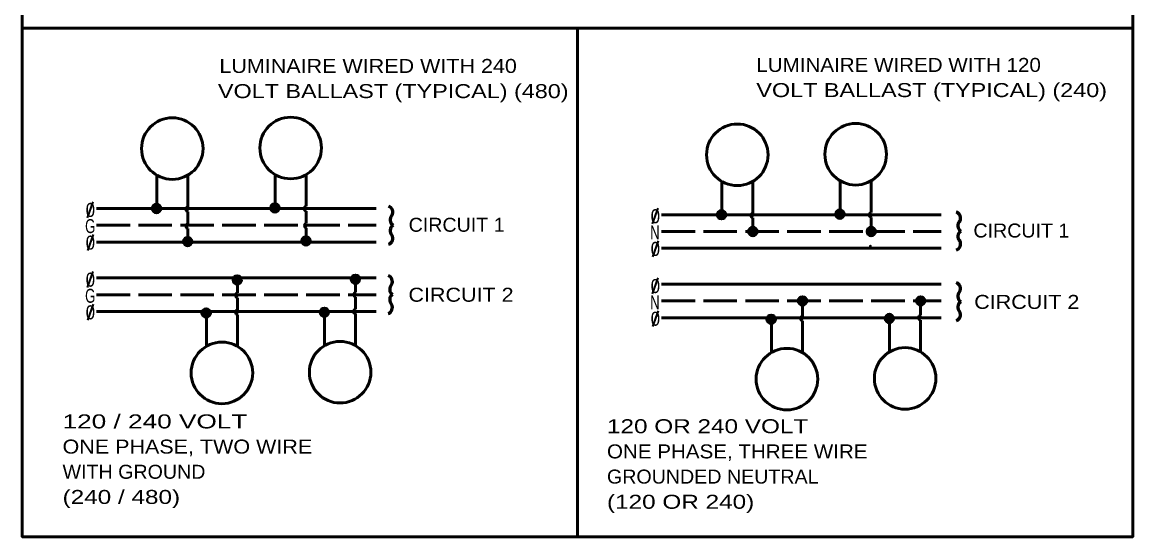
# Model space of a CAD drawing. Extents: x -217 to 639, y -295 to 249.
# Drawn here: x 241.3 to 479.6, y 13.4 to 123.7 of the extents above; entities that cross this region are included whole.
import ezdxf

# ---------------------------------------------------------------- set-up
doc = ezdxf.new("R2010")
doc.units = 0
doc.header["$LTSCALE"] = 1.2
doc.linetypes.add('LONG_DASHED', pattern=[7.5, 6, -1.5])
doc.layers.add('1', color=7, linetype='Continuous', lineweight=53)

msp = doc.modelspace()

# ---------------------------------------------------------------- hatches: boundary and pattern name
at = {"layer": '1'}
for points in [[(398.99, 78.859, 1), (397.19, 78.859, 1)], [(424.394, 78.859, 1), (422.594, 78.859, 1)], [(409.643, 63.979, 1), (407.843, 63.979, 1)], [(435.002, 63.979, 1), (433.202, 63.979, 1)]]:
    msp.add_hatch(color=256, dxfattribs=at).paths.add_polyline_path(points)

# ---------------------------------------------------------------- linework, layer by layer
for p, q in [((241.305, 122.435), (479.623, 122.435)), ((360.464, 122.435), (360.464, 13.402)), ((270.168, 83.678), (270.168, 90.949)), ((270.168, 83.678), (270.168, 90.949)), ((276.846, 84.158), (276.846, 90.948)), ((295.572, 83.805), (295.572, 91.076)), ((295.572, 83.805), (295.572, 91.076)), ((302.25, 84.285), (302.25, 91.076)), ((391.412, 82.341), (391.412, 89.612)), ((391.412, 82.341), (391.412, 89.612)), ((398.09, 82.821), (398.09, 89.612)), ((416.816, 82.469), (416.816, 89.739)), ((416.816, 82.469), (416.816, 89.739)), ((423.494, 82.948), (423.494, 89.739)), ((257.238, 83.796), (317.238, 83.796)), ((257.238, 83.796), (317.238, 83.796)), ((276.846, 80.535), (276.846, 83.107)), ((302.25, 80.663), (302.25, 83.235)), ((378.482, 82.459), (438.482, 82.459)), ((378.482, 82.459), (438.482, 82.459)), ((398.09, 78.859), (398.09, 81.77)), ((423.494, 78.859), (423.494, 81.898)), ((276.846, 76.625), (276.846, 79.479)), ((276.846, 76.625), (276.846, 79.479)), ((302.25, 76.753), (302.25, 79.606)), ((302.25, 76.753), (302.25, 79.606)), ((257.238, 76.596), (317.238, 76.596)), ((257.238, 76.596), (317.238, 76.596)), ((378.482, 75.259), (438.482, 75.259)), ((378.482, 75.259), (438.482, 75.259)), ((257.238, 68.916), (317.238, 68.916)), ((257.238, 68.916), (317.238, 68.916)), ((287.5, 68.559), (287.5, 65.705)), ((287.5, 68.559), (287.5, 65.705)), ((312.858, 68.706), (312.858, 65.852)), ((312.858, 68.706), (312.858, 65.852)), ((378.482, 67.579), (438.482, 67.579)), ((378.482, 67.579), (438.482, 67.579)), ((287.5, 64.649), (287.5, 62.076)), ((312.858, 64.796), (312.858, 62.224)), ((408.743, 63.979), (408.743, 60.739)), ((434.102, 63.979), (434.102, 60.887)), ((257.238, 61.716), (317.238, 61.716)), ((257.238, 61.716), (317.238, 61.716)), ((280.822, 61.506), (280.822, 54.235)), ((280.822, 61.506), (280.822, 54.235)), ((287.5, 61.026), (287.5, 54.235)), ((306.18, 61.653), (306.18, 54.383)), ((312.858, 61.174), (312.858, 54.383)), ((378.482, 60.379), (438.482, 60.379)), ((378.482, 60.379), (438.482, 60.379)), ((402.065, 60.169), (402.065, 52.898)), ((402.065, 60.169), (402.065, 52.898)), ((408.743, 59.689), (408.743, 52.898)), ((427.424, 60.317), (427.424, 53.046)), ((434.102, 59.837), (434.102, 53.046))]:
    msp.add_line(p, q, dxfattribs=at)
at = {"layer": '1', "lineweight": 35}
for p, q in [((256.478, 85.226), (255.241, 81.826)), ((377.722, 83.889), (376.484, 80.489)), ((256.538, 78.196), (255.3, 74.797)), ((377.781, 76.859), (376.544, 73.46)), ((256.478, 70.282), (255.241, 66.883)), ((377.722, 68.913), (376.484, 65.514)), ((256.538, 63.252), (255.3, 59.853)), ((377.781, 61.883), (376.544, 58.484))]:
    msp.add_line(p, q, dxfattribs=at)
at = {"layer": '1', "linetype": 'LONG_DASHED'}
for p, q in [((257.238, 80.196), (317.238, 80.196)), ((257.238, 80.196), (317.238, 80.196)), ((378.482, 78.859), (438.482, 78.859)), ((378.482, 78.859), (438.482, 78.859)), ((257.238, 65.316), (317.238, 65.316)), ((257.238, 65.316), (317.238, 65.316)), ((378.482, 63.979), (438.482, 63.979)), ((378.482, 63.979), (438.482, 63.979))]:
    msp.add_line(p, q, dxfattribs=at)
at = {"layer": '1'}
msp.add_lwpolyline([(241.305, 132.636), (479.623, 132.636), (479.623, 13.402), (241.305, 13.402)], close=True, dxfattribs=at)
for centre, radius in [((273.507, 96.642), 6.6), ((298.911, 96.769), 6.6), ((394.751, 95.305), 6.6), ((420.155, 95.432), 6.6), ((270.128, 83.792), 0.9), ((270.128, 83.809), 0.869), ((270.128, 83.793), 0.837), ((270.119, 83.793), 0.804), ((270.111, 83.809), 0.763), ((270.099, 83.838), 0.727), ((270.087, 83.858), 0.69), ((270.082, 83.875), 0.66), ((270.074, 83.862), 0.621), ((270.066, 83.883), 0.579), ((270.058, 83.875), 0.545), ((270.046, 83.916), 0.509), ((270.037, 83.924), 0.476), ((270.021, 83.932), 0.429), ((270.025, 83.932), 0.4), ((270.017, 83.965), 0.357), ((270.005, 83.985), 0.32), ((270, 83.993), 0.283), ((269.996, 83.998), 0.246), ((269.984, 83.998), 0.209), ((269.968, 84.002), 0.16), ((269.968, 84.002), 0.119), ((269.972, 83.998), 0.0657), ((269.964, 84.006), 0.0249), ((295.532, 83.92), 0.9), ((295.532, 83.937), 0.869), ((295.532, 83.92), 0.837), ((295.523, 83.92), 0.804), ((295.515, 83.937), 0.763), ((295.503, 83.965), 0.727), ((295.491, 83.986), 0.69), ((295.487, 84.002), 0.66), ((295.478, 83.99), 0.621), ((295.47, 84.01), 0.579), ((295.462, 84.002), 0.545), ((295.45, 84.043), 0.509), ((295.441, 84.051), 0.476), ((295.425, 84.06), 0.429), ((295.429, 84.06), 0.4), ((295.421, 84.092), 0.357), ((295.409, 84.113), 0.32), ((295.405, 84.121), 0.283), ((295.4, 84.125), 0.246), ((295.388, 84.125), 0.209), ((295.372, 84.129), 0.16), ((295.372, 84.129), 0.119), ((295.376, 84.125), 0.0657), ((295.368, 84.133), 0.0249), ((416.775, 82.583), 0.9), ((416.775, 82.6), 0.869), ((416.775, 82.583), 0.837), ((391.371, 82.455), 0.9), ((391.371, 82.472), 0.869), ((391.371, 82.456), 0.837), ((391.363, 82.456), 0.804), ((391.355, 82.472), 0.763), ((391.342, 82.501), 0.727), ((391.33, 82.521), 0.69), ((391.326, 82.538), 0.66), ((391.318, 82.525), 0.621), ((391.31, 82.546), 0.579), ((391.301, 82.538), 0.545), ((391.289, 82.579), 0.509), ((391.281, 82.587), 0.476), ((391.265, 82.595), 0.429), ((391.269, 82.595), 0.4), ((391.26, 82.628), 0.357), ((391.248, 82.648), 0.32), ((391.244, 82.657), 0.283), ((391.24, 82.661), 0.246), ((391.228, 82.661), 0.209), ((391.211, 82.665), 0.16), ((391.211, 82.665), 0.119), ((391.215, 82.661), 0.0657), ((391.207, 82.669), 0.0249), ((416.767, 82.583), 0.804), ((416.759, 82.6), 0.763), ((416.747, 82.628), 0.727), ((416.734, 82.649), 0.69), ((416.73, 82.665), 0.66), ((416.722, 82.653), 0.621), ((416.714, 82.674), 0.579), ((416.706, 82.665), 0.545), ((416.693, 82.706), 0.509), ((416.685, 82.715), 0.476), ((416.669, 82.723), 0.429), ((416.673, 82.723), 0.4), ((416.665, 82.755), 0.357), ((416.652, 82.776), 0.32), ((416.648, 82.784), 0.283), ((416.644, 82.788), 0.246), ((416.632, 82.788), 0.209), ((416.615, 82.792), 0.16), ((416.615, 82.792), 0.119), ((416.619, 82.788), 0.0657), ((416.611, 82.797), 0.0249), ((398.09, 78.859), 0.9), ((423.494, 78.859), 0.9), ((276.805, 76.705), 0.9), ((276.805, 76.705), 0.9), ((276.805, 76.722), 0.869), ((276.805, 76.722), 0.869), ((276.805, 76.706), 0.837), ((276.797, 76.706), 0.804), ((276.789, 76.722), 0.763), ((276.777, 76.751), 0.727), ((276.764, 76.771), 0.69), ((276.76, 76.788), 0.66), ((276.752, 76.776), 0.621), ((276.744, 76.796), 0.579), ((276.736, 76.788), 0.545), ((276.723, 76.829), 0.509), ((276.715, 76.837), 0.476), ((276.699, 76.845), 0.429), ((276.703, 76.845), 0.4), ((276.695, 76.878), 0.357), ((276.682, 76.898), 0.32), ((276.678, 76.907), 0.283), ((276.674, 76.911), 0.246), ((276.662, 76.911), 0.209), ((276.662, 76.911), 0.166), ((276.662, 76.911), 0.141), ((276.662, 76.911), 0.136), ((276.662, 76.911), 0.111), ((276.662, 76.911), 0.085), ((276.662, 76.911), 0.068), ((276.662, 76.911), 0.0569), ((276.662, 76.911), 0.0498), ((276.662, 76.911), 0.043), ((276.662, 76.911), 0.0431), ((276.662, 76.911), 0.0402), ((302.21, 76.833), 0.9), ((302.21, 76.833), 0.9), ((302.21, 76.85), 0.869), ((302.21, 76.85), 0.869), ((302.21, 76.833), 0.837), ((302.201, 76.833), 0.804), ((302.193, 76.85), 0.763), ((302.181, 76.879), 0.727), ((302.169, 76.899), 0.69), ((302.164, 76.915), 0.66), ((302.156, 76.903), 0.621), ((302.148, 76.924), 0.579), ((302.14, 76.915), 0.545), ((302.128, 76.956), 0.509), ((302.119, 76.965), 0.476), ((302.103, 76.973), 0.429), ((302.107, 76.973), 0.4), ((302.099, 77.006), 0.357), ((302.087, 77.026), 0.32), ((302.082, 77.034), 0.283), ((302.078, 77.038), 0.246), ((302.066, 77.038), 0.209), ((302.066, 77.038), 0.181), ((302.066, 77.038), 0.171), ((302.066, 77.038), 0.155), ((302.066, 77.038), 0.141), ((302.066, 77.038), 0.118), ((302.066, 77.038), 0.093), ((302.066, 77.038), 0.069), ((302.066, 77.038), 0.0492), ((302.066, 77.038), 0.0338), ((302.066, 77.038), 0.0319), ((302.066, 77.038), 0.0086), ((423.31, 75.702), 0.0086), ((287.459, 68.478), 0.9), ((287.459, 68.478), 0.9), ((287.459, 68.462), 0.869), ((287.459, 68.462), 0.869), ((287.459, 68.478), 0.837), ((287.451, 68.478), 0.804), ((287.443, 68.462), 0.763), ((287.43, 68.433), 0.727), ((312.817, 68.626), 0.9), ((312.817, 68.626), 0.9), ((312.817, 68.609), 0.869), ((312.817, 68.609), 0.869), ((312.817, 68.625), 0.837), ((312.809, 68.625), 0.804), ((312.801, 68.609), 0.763), ((312.789, 68.58), 0.727), ((312.776, 68.56), 0.69), ((312.772, 68.543), 0.66), ((312.764, 68.556), 0.621), ((312.756, 68.535), 0.579), ((287.418, 68.412), 0.69), ((287.414, 68.396), 0.66), ((287.406, 68.408), 0.621), ((287.398, 68.388), 0.579), ((287.389, 68.396), 0.545), ((287.377, 68.355), 0.509), ((287.369, 68.347), 0.476), ((287.353, 68.338), 0.429), ((287.357, 68.338), 0.4), ((287.348, 68.306), 0.357), ((287.336, 68.285), 0.32), ((287.332, 68.277), 0.283), ((287.328, 68.273), 0.246), ((287.316, 68.273), 0.209), ((287.316, 68.273), 0.166), ((287.316, 68.273), 0.141), ((287.316, 68.273), 0.136), ((287.316, 68.273), 0.111), ((287.316, 68.273), 0.085), ((287.316, 68.273), 0.068), ((287.316, 68.273), 0.0569), ((287.316, 68.273), 0.0498), ((287.316, 68.273), 0.043), ((287.316, 68.273), 0.0431), ((287.316, 68.273), 0.0402), ((312.748, 68.543), 0.545), ((312.735, 68.502), 0.509), ((312.727, 68.494), 0.476), ((312.711, 68.486), 0.429), ((312.715, 68.486), 0.4), ((312.707, 68.453), 0.357), ((312.694, 68.433), 0.32), ((312.69, 68.425), 0.283), ((312.69, 68.425), 0.242), ((312.69, 68.425), 0.208), ((312.69, 68.425), 0.172), ((312.69, 68.425), 0.125), ((312.69, 68.425), 0.0883), ((312.69, 68.425), 0.0552), ((312.69, 68.425), 0.0453), ((408.743, 63.979), 0.9), ((434.102, 63.979), 0.9), ((280.781, 61.392), 0.9), ((280.781, 61.375), 0.869), ((280.781, 61.391), 0.837), ((280.773, 61.391), 0.804), ((280.765, 61.375), 0.763), ((280.753, 61.346), 0.727), ((280.74, 61.326), 0.69), ((280.736, 61.309), 0.66), ((306.14, 61.539), 0.9), ((306.14, 61.522), 0.869), ((306.14, 61.539), 0.837), ((306.131, 61.539), 0.804), ((306.123, 61.522), 0.763), ((306.111, 61.494), 0.727), ((306.099, 61.473), 0.69), ((306.094, 61.457), 0.66), ((306.086, 61.469), 0.621), ((306.078, 61.448), 0.579), ((306.07, 61.457), 0.545), ((280.728, 61.321), 0.621), ((280.72, 61.301), 0.579), ((280.712, 61.309), 0.545), ((280.699, 61.268), 0.509), ((280.691, 61.26), 0.476), ((280.675, 61.252), 0.429), ((280.679, 61.252), 0.4), ((280.671, 61.219), 0.357), ((280.658, 61.198), 0.32), ((280.654, 61.19), 0.283), ((280.65, 61.186), 0.246), ((306.058, 61.416), 0.509), ((306.049, 61.407), 0.476), ((306.033, 61.399), 0.429), ((306.033, 61.399), 0.369), ((306.033, 61.399), 0.368), ((306.033, 61.399), 0.301), ((306.033, 61.399), 0.243), ((306.033, 61.399), 0.203), ((306.033, 61.399), 0.158), ((306.033, 61.399), 0.107), ((306.033, 61.399), 0.0834), ((306.033, 61.399), 0.0422), ((402.025, 60.055), 0.9), ((402.025, 60.038), 0.869), ((402.025, 60.054), 0.837), ((402.017, 60.054), 0.804), ((402.008, 60.038), 0.763), ((401.996, 60.009), 0.727), ((401.984, 59.989), 0.69), ((401.98, 59.972), 0.66), ((401.972, 59.985), 0.621), ((401.963, 59.964), 0.579), ((401.955, 59.972), 0.545), ((401.943, 59.931), 0.509), ((401.935, 59.923), 0.476), ((401.918, 59.915), 0.429), ((401.922, 59.915), 0.4), ((401.914, 59.882), 0.357), ((401.902, 59.861), 0.32), ((401.898, 59.853), 0.283), ((401.894, 59.849), 0.246), ((427.383, 60.202), 0.9), ((427.383, 60.185), 0.869), ((427.383, 60.202), 0.837), ((427.375, 60.202), 0.804), ((427.367, 60.185), 0.763), ((427.354, 60.157), 0.727), ((427.342, 60.136), 0.69), ((427.338, 60.12), 0.66), ((427.33, 60.132), 0.621), ((427.322, 60.111), 0.579), ((427.313, 60.12), 0.545), ((427.301, 60.079), 0.509), ((427.293, 60.071), 0.476), ((427.277, 60.062), 0.429), ((427.277, 60.062), 0.369), ((427.277, 60.062), 0.368), ((427.277, 60.062), 0.301), ((427.277, 60.062), 0.243), ((427.277, 60.062), 0.203), ((427.277, 60.062), 0.158), ((427.277, 60.062), 0.107), ((427.277, 60.062), 0.0834), ((427.277, 60.062), 0.0422), ((284.161, 48.542), 6.6), ((309.519, 48.69), 6.6), ((405.404, 47.205), 6.6), ((430.763, 47.353), 6.6)]:
    msp.add_circle(centre, radius, dxfattribs=at)
for centre in [(277.01, 83.636), (302.414, 83.763), (398.253, 82.299), (423.657, 82.426), (277.044, 80.007), (302.448, 80.135), (287.698, 65.177), (313.056, 65.324), (287.663, 61.548), (313.022, 61.696), (408.907, 60.211), (434.265, 60.359)]:
    msp.add_arc(centre, 0.558, 108.90604, 251.09396, dxfattribs=at)
at = {"layer": '1', "lineweight": 60}
for centre, radius, start, end in [((319.471, 83), 1.363, 330.39195, 71.42822), ((321.704, 81.337), 1.445, 136.63658, 231.64318), ((441.313, 81.746), 1.363, 330.39195, 71.42822), ((443.546, 80.083), 1.445, 136.63658, 231.64318), ((321.704, 79.071), 1.445, 128.35682, 223.36342), ((443.546, 77.817), 1.445, 128.35682, 223.36342), ((319.471, 77.408), 1.363, 288.57178, 29.60805), ((441.313, 76.154), 1.363, 288.57178, 29.60805), ((319.379, 68.143), 1.363, 330.39195, 71.42822), ((321.611, 66.479), 1.445, 136.63658, 231.64318), ((441.284, 66.607), 1.363, 330.39195, 71.42822), ((321.611, 64.214), 1.445, 128.35682, 223.36342), ((443.516, 64.943), 1.445, 136.63658, 231.64318), ((319.379, 62.55), 1.363, 288.57178, 29.60805), ((443.516, 62.677), 1.445, 128.35682, 223.36342), ((441.284, 61.014), 1.363, 288.57178, 29.60805)]:
    msp.add_arc(centre, radius, start, end, dxfattribs=at)

# ---------------------------------------------------------------- texts
at = {"layer": '1'}
for s, width, p in [('LUMINAIRE WIRED WITH 240', 1.15, (283.62, 112.862)), ('LUMINAIRE WIRED WITH 120', 1.1, (398.846, 113.083)), ('VOLT BALLAST (TYPICAL) (480)', 1.25, (283.304, 107.462)), ('VOLT BALLAST (TYPICAL) (240)', 1.25, (398.846, 107.683)), ('0', 0.9, (254.926, 81.978)), ('0', 0.9, (376.17, 80.641)), ('G', 0.7, (254.806, 78.519)), ('CIRCUIT 1', 1.05, (324.231, 78.802)), ('N', 0.7, (376.05, 77.183)), ('CIRCUIT 1', 1.05, (445.423, 77.573)), ('0', 0.9, (254.926, 74.971)), ('0', 0.9, (376.17, 73.634)), ('0', 0.9, (254.926, 67.034)), ('CIRCUIT 2', 1.15, (324.189, 63.8)), ('0', 0.9, (376.17, 65.665)), ('G', 0.7, (254.806, 63.576)), ('N', 0.7, (376.05, 62.207)), ('CIRCUIT 2', 1.15, (445.598, 62.265)), ('0', 0.9, (254.926, 60.027)), ('0', 0.9, (376.17, 58.658)), ('120 / 240 VOLT', 1.4, (249.963, 36.64)), ('120 OR 240 VOLT', 1.3, (366.79, 35.606)), ('ONE PHASE, TWO WIRE', 1.15, (249.963, 31.24)), ('ONE PHASE, THREE WIRE', 1.1, (366.79, 30.206)), ('WITH GROUND', 1.05, (249.963, 25.84)), ('GROUNDED NEUTRAL', 1.05, (366.79, 24.806)), ('(240 / 480)', 1.3, (249.963, 20.44)), ('(120 OR 240)', 1.3, (366.79, 19.406))]:
    msp.add_text(s, height=3, dxfattribs=dict(at, width=width)).set_placement(p)

doc.saveas('drawing.dxf')
